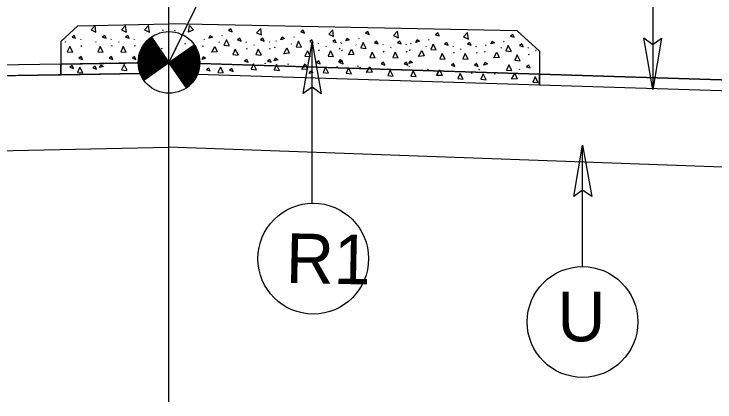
# Model space of a CAD drawing. Extents: x 2176156 to 2177167, y 76401 to 76644.
# Drawn here: x 2176318.14 to 2176334.56, y 76553.5 to 76562.57 of the extents above; entities that cross this region are included whole.
import ezdxf

# ---------------------------------------------------------------- set-up
doc = ezdxf.new("R2010")
doc.units = 0
for name, color, linetype in [('Exist Roads Change in Surface', 7, 'Continuous'), ('Exist Roads Curbs', 7, 'Continuous'), ('Exist Roads Soil', 7, 'Continuous'), ('Old_Level_3', 7, 'Continuous'), ('Prop North Arrow NAD83 for Plan Sheets CELL', 7, 'Continuous'), ('Sheet Plan CELL', 7, 'Continuous')]:
    doc.layers.add(name, color=color, linetype=linetype)

msp = doc.modelspace()

# ---------------------------------------------------------------- linework, layer by layer
at = {"layer": 'Exist Roads Change in Surface'}
for p, q in [((2176321.635, 76562.179), (2176321.625, 76562.203)), ((2176321.902, 76562.179), (2176321.913, 76562.203)), ((2176319.705, 76561.99), (2176319.694, 76561.974)), ((2176320.418, 76561.99), (2176320.407, 76561.974)), ((2176320.957, 76561.99), (2176320.947, 76561.974)), ((2176321.357, 76562.034), (2176321.769, 76561.442)), ((2176322.581, 76561.99), (2176322.591, 76561.974)), ((2176323.015, 76562.075), (2176323.004, 76562.059)), ((2176324.703, 76562.042), (2176324.692, 76562.026)), ((2176326.218, 76562.011), (2176326.208, 76561.995)), ((2176327.86, 76561.979), (2176327.849, 76561.963)), ((2176319.346, 76561.923), (2176319.336, 76561.907)), ((2176319.725, 76561.815), (2176319.715, 76561.839)), ((2176320.059, 76561.923), (2176320.048, 76561.907)), ((2176320.438, 76561.815), (2176320.427, 76561.839)), ((2176320.598, 76561.923), (2176320.588, 76561.907)), ((2176320.977, 76561.815), (2176320.967, 76561.839)), ((2176321.393, 76561.87), (2176321.382, 76561.894)), ((2176321.769, 76561.442), (2176322.361, 76561.854)), ((2176322.145, 76561.87), (2176322.156, 76561.894)), ((2176322.56, 76561.815), (2176322.571, 76561.839)), ((2176322.94, 76561.923), (2176322.95, 76561.907)), ((2176323.583, 76561.923), (2176323.572, 76561.907)), ((2176323.763, 76561.855), (2176323.753, 76561.839)), ((2176324.122, 76561.923), (2176324.112, 76561.907)), ((2176324.249, 76561.781), (2176324.259, 76561.805)), ((2176324.269, 76561.957), (2176324.28, 76561.941)), ((2176324.628, 76561.889), (2176324.638, 76561.873)), ((2176325.271, 76561.889), (2176325.26, 76561.873)), ((2176325.452, 76561.821), (2176325.441, 76561.805)), ((2176325.784, 76561.926), (2176325.795, 76561.91)), ((2176325.81, 76561.889), (2176325.8, 76561.873)), ((2176326.143, 76561.858), (2176326.154, 76561.843)), ((2176326.787, 76561.859), (2176326.776, 76561.843)), ((2176327.326, 76561.859), (2176327.315, 76561.843)), ((2176327.426, 76561.893), (2176327.437, 76561.877)), ((2176327.785, 76561.826), (2176327.795, 76561.81)), ((2176328.428, 76561.826), (2176328.417, 76561.81)), ((2176328.967, 76561.826), (2176328.957, 76561.81)), ((2176329.184, 76561.858), (2176329.194, 76561.842)), ((2176329.618, 76561.943), (2176329.607, 76561.927)), ((2176321.609, 76561.754), (2176321.598, 76561.777)), ((2176321.929, 76561.754), (2176321.94, 76561.777)), ((2176323.603, 76561.747), (2176323.592, 76561.771)), ((2176324.142, 76561.747), (2176324.132, 76561.771)), ((2176325.291, 76561.714), (2176325.281, 76561.738)), ((2176325.764, 76561.751), (2176325.775, 76561.775)), ((2176325.831, 76561.714), (2176325.82, 76561.738)), ((2176326.807, 76561.683), (2176326.796, 76561.707)), ((2176326.967, 76561.791), (2176326.956, 76561.775)), ((2176327.346, 76561.683), (2176327.335, 76561.707)), ((2176327.406, 76561.718), (2176327.416, 76561.742)), ((2176328.448, 76561.65), (2176328.438, 76561.674)), ((2176328.609, 76561.758), (2176328.598, 76561.742)), ((2176328.988, 76561.65), (2176328.977, 76561.674)), ((2176329.164, 76561.683), (2176329.174, 76561.707)), ((2176329.543, 76561.791), (2176329.553, 76561.775)), ((2176330.186, 76561.791), (2176330.175, 76561.775)), ((2176330.206, 76561.615), (2176330.195, 76561.639)), ((2176330.366, 76561.723), (2176330.356, 76561.707)), ((2176321.276, 76561.583), (2176321.265, 76561.567)), ((2176322.262, 76561.583), (2176322.273, 76561.567)), ((2176321.176, 76561.032), (2176321.769, 76561.442)), ((2176321.769, 76561.442), (2176321.176, 76561.032)), ((2176322.181, 76560.85), (2176321.769, 76561.442)), ((2176324.03, 76561.399), (2176324.02, 76561.423)), ((2176324.569, 76561.385), (2176324.559, 76561.409)), ((2176325.716, 76561.322), (2176325.706, 76561.346)), ((2176326.19, 76561.347), (2176326.201, 76561.371)), ((2176326.256, 76561.308), (2176326.246, 76561.332)), ((2176327.394, 76561.356), (2176327.383, 76561.341)), ((2176327.231, 76561.253), (2176327.221, 76561.277)), ((2176327.77, 76561.239), (2176327.76, 76561.263)), ((2176327.83, 76561.272), (2176327.842, 76561.296)), ((2176328.871, 76561.178), (2176328.861, 76561.202)), ((2176329.034, 76561.282), (2176329.023, 76561.266)), ((2176329.41, 76561.164), (2176329.4, 76561.188)), ((2176329.587, 76561.192), (2176329.598, 76561.216)), ((2176329.968, 76561.29), (2176329.979, 76561.274))]:
    msp.add_line(p, q, dxfattribs=at)
for points in [[(2176320.059, 76562.152), (2176320.038, 76562.304), (2176319.943, 76562.206), (2176320.057, 76562.153)], [(2176320.772, 76562.152), (2176320.751, 76562.304), (2176320.655, 76562.206), (2176320.769, 76562.153)], [(2176321.311, 76562.152), (2176321.29, 76562.304), (2176321.195, 76562.206), (2176321.309, 76562.153)], [(2176322.227, 76562.152), (2176322.248, 76562.304), (2176322.343, 76562.206), (2176322.229, 76562.153)], [(2176323.251, 76562.162), (2176323.219, 76562.228), (2176323.166, 76562.188), (2176323.251, 76562.162)], [(2176323.937, 76562.084), (2176323.916, 76562.237), (2176323.82, 76562.138), (2176323.934, 76562.085)], [(2176324.94, 76562.128), (2176324.908, 76562.195), (2176324.854, 76562.155), (2176324.94, 76562.128)], [(2176325.625, 76562.051), (2176325.604, 76562.203), (2176325.509, 76562.104), (2176325.623, 76562.052)], [(2176326.455, 76562.098), (2176326.423, 76562.164), (2176326.37, 76562.124), (2176326.455, 76562.098)], [(2176327.141, 76562.02), (2176327.119, 76562.173), (2176327.024, 76562.074), (2176327.138, 76562.021)], [(2176328.097, 76562.065), (2176328.065, 76562.132), (2176328.011, 76562.092), (2176328.097, 76562.065)], [(2176328.782, 76561.987), (2176328.761, 76562.14), (2176328.666, 76562.041), (2176328.78, 76561.988)], [(2176319.583, 76562.009), (2176319.551, 76562.076), (2176319.498, 76562.036), (2176319.583, 76562.009)], [(2176320.296, 76562.009), (2176320.264, 76562.076), (2176320.21, 76562.036), (2176320.296, 76562.009)], [(2176320.835, 76562.009), (2176320.803, 76562.076), (2176320.75, 76562.036), (2176320.835, 76562.009)], [(2176321.4, 76561.972), (2176321.136, 76561.788)], [(2176321.392, 76561.984), (2176321.153, 76561.817)], [(2176321.384, 76561.996), (2176321.172, 76561.848)], [(2176321.376, 76562.007), (2176321.199, 76561.885)], [(2176321.367, 76562.019), (2176321.233, 76561.926)], [(2176321.359, 76562.031), (2176321.295, 76561.986)], [(2176322.703, 76562.009), (2176322.735, 76562.076), (2176322.788, 76562.036), (2176322.703, 76562.009)], [(2176323.185, 76561.834), (2176323.113, 76561.97), (2176323.057, 76561.845), (2176323.182, 76561.834)], [(2176323.461, 76561.941), (2176323.429, 76562.008), (2176323.375, 76561.968), (2176323.461, 76561.941)], [(2176324, 76561.941), (2176323.968, 76562.008), (2176323.915, 76561.968), (2176324, 76561.941)], [(2176324.391, 76561.975), (2176324.423, 76562.042), (2176324.476, 76562.002), (2176324.391, 76561.975)], [(2176325.149, 76561.908), (2176325.117, 76561.974), (2176325.064, 76561.934), (2176325.149, 76561.908)], [(2176325.688, 76561.908), (2176325.656, 76561.974), (2176325.603, 76561.934), (2176325.688, 76561.908)], [(2176325.907, 76561.945), (2176325.939, 76562.011), (2176325.992, 76561.972), (2176325.907, 76561.945)], [(2176327.548, 76561.912), (2176327.58, 76561.979), (2176327.633, 76561.939), (2176327.548, 76561.912)], [(2176329.855, 76562.03), (2176329.823, 76562.096), (2176329.769, 76562.056), (2176329.855, 76562.03)], [(2176319.516, 76561.682), (2176319.444, 76561.817), (2176319.388, 76561.692), (2176319.514, 76561.682)], [(2176320.229, 76561.682), (2176320.157, 76561.817), (2176320.101, 76561.692), (2176320.226, 76561.682)], [(2176320.768, 76561.682), (2176320.697, 76561.817), (2176320.641, 76561.692), (2176320.766, 76561.682)], [(2176321.516, 76561.806), (2176321.049, 76561.481)], [(2176321.507, 76561.818), (2176321.05, 76561.5)], [(2176321.499, 76561.83), (2176321.052, 76561.519)], [(2176321.491, 76561.842), (2176321.054, 76561.538)], [(2176321.483, 76561.854), (2176321.057, 76561.557)], [(2176321.474, 76561.865), (2176321.06, 76561.577)], [(2176321.466, 76561.877), (2176321.065, 76561.598)], [(2176321.458, 76561.889), (2176321.07, 76561.619)], [(2176321.45, 76561.901), (2176321.076, 76561.641)], [(2176321.441, 76561.913), (2176321.083, 76561.663)], [(2176321.433, 76561.924), (2176321.09, 76561.686)], [(2176321.425, 76561.936), (2176321.099, 76561.709)], [(2176321.417, 76561.948), (2176321.109, 76561.734)], [(2176321.408, 76561.96), (2176321.122, 76561.761)], [(2176322.364, 76561.848), (2176322.364, 76561.848), (2176321.773, 76561.437)], [(2176322.373, 76561.837), (2176321.781, 76561.425)], [(2176322.379, 76561.824), (2176321.789, 76561.413)], [(2176322.388, 76561.812), (2176321.797, 76561.401)], [(2176322.769, 76561.682), (2176322.841, 76561.817), (2176322.897, 76561.692), (2176322.772, 76561.682)], [(2176324.873, 76561.801), (2176324.801, 76561.937), (2176324.745, 76561.811), (2176324.87, 76561.801)], [(2176326.389, 76561.77), (2176326.317, 76561.906), (2176326.261, 76561.781), (2176326.386, 76561.77)], [(2176326.664, 76561.877), (2176326.632, 76561.944), (2176326.579, 76561.904), (2176326.664, 76561.877)], [(2176327.204, 76561.877), (2176327.172, 76561.944), (2176327.118, 76561.904), (2176327.204, 76561.877)], [(2176328.03, 76561.738), (2176327.958, 76561.873), (2176327.902, 76561.748), (2176328.027, 76561.738)], [(2176328.306, 76561.845), (2176328.274, 76561.911), (2176328.221, 76561.871), (2176328.306, 76561.845)], [(2176328.845, 76561.845), (2176328.813, 76561.911), (2176328.76, 76561.871), (2176328.845, 76561.845)], [(2176329.306, 76561.877), (2176329.338, 76561.943), (2176329.391, 76561.904), (2176329.306, 76561.877)], [(2176329.788, 76561.702), (2176329.716, 76561.838), (2176329.66, 76561.713), (2176329.785, 76561.702)], [(2176330.064, 76561.809), (2176330.032, 76561.876), (2176329.978, 76561.836), (2176330.064, 76561.809)], [(2176321.524, 76561.794), (2176321.048, 76561.463)], [(2176321.532, 76561.783), (2176321.048, 76561.446)], [(2176321.54, 76561.771), (2176321.049, 76561.429)], [(2176321.548, 76561.759), (2176321.049, 76561.411)], [(2176321.557, 76561.747), (2176321.049, 76561.394)], [(2176321.565, 76561.735), (2176321.051, 76561.377)], [(2176321.573, 76561.723), (2176321.053, 76561.361)], [(2176321.581, 76561.712), (2176321.054, 76561.345)], [(2176321.59, 76561.7), (2176321.057, 76561.329)], [(2176321.598, 76561.688), (2176321.06, 76561.314)], [(2176321.606, 76561.676), (2176321.063, 76561.298)], [(2176321.614, 76561.664), (2176321.066, 76561.283)], [(2176321.623, 76561.652), (2176321.069, 76561.267)], [(2176321.631, 76561.641), (2176321.073, 76561.253)], [(2176322.395, 76561.799), (2176321.806, 76561.389)], [(2176322.402, 76561.787), (2176321.814, 76561.378)], [(2176322.408, 76561.774), (2176321.822, 76561.366)], [(2176322.415, 76561.761), (2176321.83, 76561.354)], [(2176322.422, 76561.748), (2176321.839, 76561.342)], [(2176322.428, 76561.735), (2176321.847, 76561.33)], [(2176322.434, 76561.721), (2176321.855, 76561.318)], [(2176322.439, 76561.707), (2176321.863, 76561.307)], [(2176322.445, 76561.694), (2176321.871, 76561.295)], [(2176322.449, 76561.679), (2176321.88, 76561.283)], [(2176322.455, 76561.665), (2176321.888, 76561.271)], [(2176322.459, 76561.651), (2176321.896, 76561.259)], [(2176323.394, 76561.614), (2176323.322, 76561.75), (2176323.266, 76561.625), (2176323.391, 76561.614)], [(2176323.933, 76561.614), (2176323.861, 76561.75), (2176323.806, 76561.625), (2176323.931, 76561.614)], [(2176324.458, 76561.648), (2176324.53, 76561.784), (2176324.586, 76561.658), (2176324.46, 76561.648)], [(2176325.082, 76561.58), (2176325.01, 76561.716), (2176324.954, 76561.591), (2176325.08, 76561.58)], [(2176325.622, 76561.58), (2176325.55, 76561.716), (2176325.494, 76561.591), (2176325.619, 76561.58)], [(2176325.973, 76561.618), (2176326.045, 76561.753), (2176326.101, 76561.628), (2176325.976, 76561.618)], [(2176326.598, 76561.55), (2176326.526, 76561.686), (2176326.47, 76561.561), (2176326.595, 76561.55)], [(2176327.137, 76561.55), (2176327.065, 76561.686), (2176327.009, 76561.561), (2176327.134, 76561.55)], [(2176327.615, 76561.585), (2176327.687, 76561.721), (2176327.743, 76561.595), (2176327.617, 76561.585)], [(2176328.239, 76561.517), (2176328.167, 76561.653), (2176328.111, 76561.528), (2176328.237, 76561.517)], [(2176328.779, 76561.517), (2176328.707, 76561.653), (2176328.651, 76561.528), (2176328.776, 76561.517)], [(2176329.373, 76561.55), (2176329.444, 76561.685), (2176329.5, 76561.56), (2176329.375, 76561.55)], [(2176319.744, 76561.514), (2176319.712, 76561.58), (2176319.659, 76561.54), (2176319.744, 76561.514)], [(2176320.457, 76561.514), (2176320.425, 76561.58), (2176320.371, 76561.54), (2176320.457, 76561.514)], [(2176320.996, 76561.514), (2176320.964, 76561.58), (2176320.911, 76561.54), (2176320.996, 76561.514)], [(2176321.639, 76561.629), (2176321.078, 76561.238)], [(2176321.647, 76561.617), (2176321.082, 76561.223)], [(2176321.656, 76561.605), (2176321.088, 76561.21)], [(2176321.664, 76561.593), (2176321.092, 76561.195)], [(2176321.672, 76561.581), (2176321.097, 76561.182)], [(2176321.68, 76561.569), (2176321.103, 76561.168)], [(2176321.688, 76561.558), (2176321.109, 76561.154)], [(2176321.697, 76561.546), (2176321.114, 76561.141)], [(2176321.705, 76561.534), (2176321.121, 76561.128)], [(2176321.713, 76561.522), (2176321.127, 76561.114)], [(2176321.721, 76561.51), (2176321.134, 76561.101)], [(2176321.73, 76561.499), (2176321.141, 76561.089)], [(2176321.738, 76561.487), (2176321.148, 76561.076)], [(2176321.746, 76561.475), (2176321.156, 76561.064)], [(2176322.463, 76561.636), (2176321.904, 76561.247)], [(2176322.468, 76561.622), (2176321.913, 76561.236)], [(2176322.47, 76561.606), (2176321.921, 76561.224)], [(2176322.473, 76561.591), (2176321.929, 76561.212)], [(2176322.476, 76561.575), (2176321.937, 76561.2)], [(2176322.479, 76561.56), (2176321.946, 76561.188)], [(2176322.482, 76561.544), (2176321.954, 76561.176)], [(2176322.484, 76561.528), (2176321.962, 76561.165)], [(2176322.486, 76561.511), (2176321.97, 76561.153)], [(2176322.487, 76561.495), (2176321.979, 76561.141)], [(2176322.489, 76561.479), (2176321.987, 76561.129)], [(2176322.542, 76561.514), (2176322.574, 76561.58), (2176322.627, 76561.54), (2176322.542, 76561.514)], [(2176323.622, 76561.446), (2176323.59, 76561.513), (2176323.536, 76561.473), (2176323.622, 76561.446)], [(2176324.161, 76561.446), (2176324.129, 76561.513), (2176324.076, 76561.473), (2176324.161, 76561.446)], [(2176324.23, 76561.48), (2176324.262, 76561.547), (2176324.315, 76561.507), (2176324.23, 76561.48)], [(2176325.31, 76561.413), (2176325.278, 76561.479), (2176325.225, 76561.439), (2176325.31, 76561.413)], [(2176325.746, 76561.45), (2176325.778, 76561.516), (2176325.831, 76561.476), (2176325.746, 76561.45)], [(2176325.849, 76561.413), (2176325.817, 76561.479), (2176325.764, 76561.439), (2176325.849, 76561.413)], [(2176327.387, 76561.417), (2176327.419, 76561.483), (2176327.472, 76561.443), (2176327.387, 76561.417)], [(2176329.997, 76561.482), (2176329.925, 76561.618), (2176329.869, 76561.493), (2176329.994, 76561.482)], [(2176319.533, 76561.303), (2176319.503, 76561.371), (2176319.448, 76561.332), (2176319.533, 76561.303)], [(2176319.752, 76561.2), (2176319.68, 76561.336), (2176319.624, 76561.211), (2176319.749, 76561.2)], [(2176320.072, 76561.289), (2176320.042, 76561.357), (2176319.988, 76561.318), (2176320.072, 76561.289)], [(2176320.142, 76561.321), (2176320.176, 76561.387), (2176320.228, 76561.346), (2176320.142, 76561.321)], [(2176320.787, 76561.256), (2176320.716, 76561.392), (2176320.66, 76561.267), (2176320.785, 76561.256)], [(2176321.754, 76561.463), (2176321.163, 76561.051)], [(2176321.763, 76561.451), (2176321.171, 76561.039), (2176321.171, 76561.039)], [(2176322.489, 76561.461), (2176321.995, 76561.117)], [(2176322.49, 76561.444), (2176322.003, 76561.105)], [(2176322.489, 76561.426), (2176322.011, 76561.094)], [(2176322.489, 76561.408), (2176322.02, 76561.082)], [(2176322.488, 76561.39), (2176322.028, 76561.07)], [(2176322.486, 76561.371), (2176322.036, 76561.058)], [(2176322.484, 76561.352), (2176322.044, 76561.046)], [(2176322.481, 76561.333), (2176322.053, 76561.034)], [(2176322.478, 76561.313), (2176322.061, 76561.023)], [(2176322.734, 76561.244), (2176322.704, 76561.312), (2176322.649, 76561.273), (2176322.734, 76561.244)], [(2176323.044, 76561.2), (2176322.972, 76561.336), (2176322.916, 76561.211), (2176323.041, 76561.2)], [(2176323.817, 76561.271), (2176323.749, 76561.409), (2176323.69, 76561.285), (2176323.815, 76561.271)], [(2176324.357, 76561.257), (2176324.288, 76561.395), (2176324.229, 76561.271), (2176324.354, 76561.257)], [(2176324.882, 76561.277), (2176324.957, 76561.411), (2176325.01, 76561.285), (2176324.884, 76561.277)], [(2176325.504, 76561.194), (2176325.436, 76561.332), (2176325.377, 76561.208), (2176325.501, 76561.194)], [(2176326.043, 76561.18), (2176325.975, 76561.318), (2176325.916, 76561.194), (2176326.041, 76561.18)], [(2176326.396, 76561.208), (2176326.471, 76561.342), (2176326.524, 76561.216), (2176326.398, 76561.208)], [(2176326.825, 76561.382), (2176326.793, 76561.449), (2176326.74, 76561.409), (2176326.825, 76561.382)], [(2176327.365, 76561.382), (2176327.333, 76561.449), (2176327.28, 76561.409), (2176327.365, 76561.382)], [(2176328.467, 76561.349), (2176328.435, 76561.416), (2176328.382, 76561.376), (2176328.467, 76561.349)], [(2176329.006, 76561.349), (2176328.974, 76561.416), (2176328.921, 76561.376), (2176329.006, 76561.349)], [(2176329.145, 76561.382), (2176329.177, 76561.448), (2176329.23, 76561.408), (2176329.145, 76561.382)], [(2176329.799, 76561.252), (2176329.727, 76561.387), (2176329.671, 76561.262), (2176329.796, 76561.252)], [(2176330.225, 76561.314), (2176330.193, 76561.381), (2176330.139, 76561.341), (2176330.225, 76561.314)], [(2176322.474, 76561.293), (2176322.069, 76561.011)], [(2176322.469, 76561.272), (2176322.077, 76560.999)], [(2176322.463, 76561.25), (2176322.086, 76560.987)], [(2176322.457, 76561.228), (2176322.094, 76560.975)], [(2176322.449, 76561.205), (2176322.102, 76560.963)], [(2176322.44, 76561.181), (2176322.11, 76560.952)], [(2176322.43, 76561.157), (2176322.119, 76560.94)], [(2176323.273, 76561.23), (2176323.243, 76561.298), (2176323.189, 76561.259), (2176323.273, 76561.23)], [(2176325.053, 76561.184), (2176325.086, 76561.25), (2176325.139, 76561.209), (2176325.053, 76561.184)], [(2176327.018, 76561.125), (2176326.95, 76561.263), (2176326.891, 76561.139), (2176327.016, 76561.125)], [(2176327.558, 76561.111), (2176327.489, 76561.249), (2176327.43, 76561.125), (2176327.555, 76561.111)], [(2176328.036, 76561.134), (2176328.111, 76561.268), (2176328.164, 76561.141), (2176328.039, 76561.134)], [(2176328.659, 76561.05), (2176328.59, 76561.188), (2176328.531, 76561.064), (2176328.656, 76561.05)], [(2176329.198, 76561.036), (2176329.129, 76561.174), (2176329.07, 76561.05), (2176329.195, 76561.036)], [(2176329.792, 76561.054), (2176329.868, 76561.188), (2176329.92, 76561.061), (2176329.795, 76561.053)], [(2176322.419, 76561.131), (2176322.127, 76560.928)], [(2176322.406, 76561.105), (2176322.135, 76560.916)], [(2176322.389, 76561.075), (2176322.143, 76560.904)], [(2176322.37, 76561.044), (2176322.151, 76560.892)], [(2176322.345, 76561.01), (2176322.16, 76560.881)], [(2176330.415, 76560.97), (2176330.346, 76561.108), (2176330.287, 76560.984), (2176330.412, 76560.97)], [(2176322.313, 76560.969), (2176322.168, 76560.869)], [(2176322.26, 76560.915), (2176322.176, 76560.857)]]:
    msp.add_lwpolyline(points, dxfattribs=at)
msp.add_circle((2176321.769, 76561.443), 0.721, dxfattribs=at)
for start, end in [(124.8249, 214.8249), (304.8249, 34.8249)]:
    msp.add_arc((2176321.769, 76561.443), 0.721, start, end, dxfattribs=at)
at = {"layer": 'Exist Roads Curbs'}
for p, q in [((2176319.239, 76561.404), (2176307.239, 76561.226)), ((2176319.239, 76561.404), (2176307.239, 76561.226)), ((2176319.239, 76561.404), (2176321.769, 76561.442)), ((2176321.048, 76561.431), (2176319.239, 76561.404)), ((2176319.239, 76561.154), (2176319.239, 76561.404)), ((2176319.239, 76561.404), (2176319.239, 76561.154)), ((2176321.049, 76561.394), (2176321.049, 76561.394)), ((2176321.054, 76561.345), (2176321.055, 76561.345)), ((2176321.769, 76561.442), (2176330.444, 76561.171)), ((2176322.478, 76561.313), (2176322.478, 76561.313)), ((2176322.481, 76561.333), (2176322.481, 76561.333)), ((2176322.488, 76561.39), (2176322.488, 76561.39)), ((2176330.444, 76561.171), (2176322.489, 76561.42)), ((2176322.489, 76561.408), (2176322.489, 76561.408)), ((2176321.097, 76561.182), (2176306.983, 76560.972)), ((2176319.239, 76561.154), (2176321.097, 76561.182)), ((2176321.069, 76561.267), (2176321.069, 76561.267)), ((2176321.073, 76561.253), (2176321.073, 76561.253)), ((2176321.082, 76561.223), (2176321.082, 76561.223)), ((2176322.436, 76561.171), (2176342.704, 76560.539)), ((2176322.436, 76561.171), (2176330.444, 76560.921)), ((2176322.449, 76561.205), (2176322.449, 76561.205)), ((2176322.457, 76561.228), (2176322.457, 76561.228)), ((2176322.469, 76561.272), (2176322.469, 76561.271)), ((2176322.474, 76561.293), (2176322.474, 76561.292)), ((2176330.444, 76561.171), (2176342.444, 76560.797)), ((2176342.444, 76560.797), (2176330.444, 76561.171)), ((2176330.444, 76561.171), (2176330.444, 76560.921)), ((2176330.444, 76560.921), (2176330.444, 76561.171)), ((2176330.444, 76560.921), (2176338.626, 76560.666))]:
    msp.add_line(p, q, dxfattribs=at)
for points in [[(2176321.049, 76561.394), (2176321.049, 76561.394)], [(2176321.055, 76561.345), (2176321.054, 76561.345)], [(2176322.478, 76561.313), (2176322.478, 76561.313)], [(2176322.481, 76561.333), (2176322.481, 76561.333)], [(2176322.488, 76561.39), (2176322.488, 76561.39)], [(2176322.489, 76561.408), (2176322.489, 76561.408)], [(2176307.25, 76560.736), (2176308.813, 76560.76), (2176309.529, 76560.77), (2176310.927, 76560.791), (2176312.319, 76560.812), (2176312.319, 76561.052), (2176319.239, 76561.154)], [(2176321.07, 76561.267), (2176321.069, 76561.267)], [(2176321.073, 76561.253), (2176321.073, 76561.253)], [(2176321.082, 76561.223), (2176321.082, 76561.223)], [(2176322.449, 76561.205), (2176322.449, 76561.205)], [(2176322.457, 76561.228), (2176322.457, 76561.228)], [(2176322.469, 76561.272), (2176322.469, 76561.272)], [(2176322.474, 76561.293), (2176322.474, 76561.293)], [(2176330.444, 76560.921), (2176330.444, 76560.921)]]:
    msp.add_lwpolyline(points, dxfattribs=at)
for start, end in [(180.9136, 182.5146), (182.5146, 183.8761), (183.8895, 187.8094), (187.8245, 190.3336), (190.3336, 191.5882), (347.9775, 349.598), (349.5984, 351.2038), (351.2196, 352.7539), (352.7539, 355.7778), (355.8127, 357.2394), (357.2652, 358.1523), (191.5882, 194.0754), (194.0907, 195.2968), (195.2976, 197.7127), (197.7154, 201.2126), (337.8613, 340.731), (340.7368, 342.6429), (342.646, 346.2404), (346.2648, 347.9455)]:
    msp.add_arc((2176321.769, 76561.443), 0.721, start, end, dxfattribs=at)
at = {"layer": 'Exist Roads Soil'}
for p, q in [((2176319.239, 76561.936), (2176319.634, 76562.299)), ((2176319.634, 76562.299), (2176321.769, 76562.342)), ((2176329.927, 76562.179), (2176321.769, 76562.342)), ((2176330.444, 76561.703), (2176329.927, 76562.179)), ((2176319.239, 76561.936), (2176319.239, 76561.154)), ((2176330.444, 76561.703), (2176330.444, 76560.921))]:
    msp.add_line(p, q, dxfattribs=at)
at = {"layer": 'Old_Level_3'}
msp.add_line((2176321.769, 76553.503), (2176321.769, 76572.796), dxfattribs=at)
at = {"layer": 'Prop North Arrow NAD83 for Plan Sheets CELL'}
for p, q in [((2176324.492, 76567.05), (2176321.769, 76561.442)), ((2176333.1, 76563.616), (2176333.1, 76560.812)), ((2176325.12, 76558.151), (2176325.12, 76561.916)), ((2176331.454, 76556.669), (2176331.454, 76559.511))]:
    msp.add_line(p, q, dxfattribs=at)
for points in [[(2176333.307, 76562.012), (2176333.1, 76560.812), (2176332.887, 76562.019), (2176333.1, 76561.866)], [(2176324.914, 76560.716), (2176325.12, 76561.916), (2176325.334, 76560.71), (2176325.12, 76560.863)], [(2176331.248, 76558.311), (2176331.454, 76559.511), (2176331.668, 76558.305), (2176331.454, 76558.458)]]:
    msp.add_lwpolyline(points, close=True, dxfattribs=at)
for centre in [(2176325.147, 76556.855), (2176331.454, 76555.373)]:
    msp.add_circle(centre, 1.296, dxfattribs=at)
at = {"layer": 'Sheet Plan CELL'}
for p in [(2176312.319, 76559.266), (2176338.626, 76558.851)]:
    msp.add_line(p, (2176321.769, 76559.462), dxfattribs=at)

# ---------------------------------------------------------------- texts
at = {"layer": 'Prop North Arrow NAD83 for Plan Sheets CELL'}
for s, rotation, p in [('R1', 358.8249, (2176324.499, 76556.289)), ('U', 0.0003, (2176330.868, 76554.919))]:
    msp.add_text(s, height=1.16, rotation=rotation, dxfattribs=at).set_placement(p)

doc.saveas('drawing.dxf')
